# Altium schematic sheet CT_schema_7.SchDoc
size 299 x 271 mm
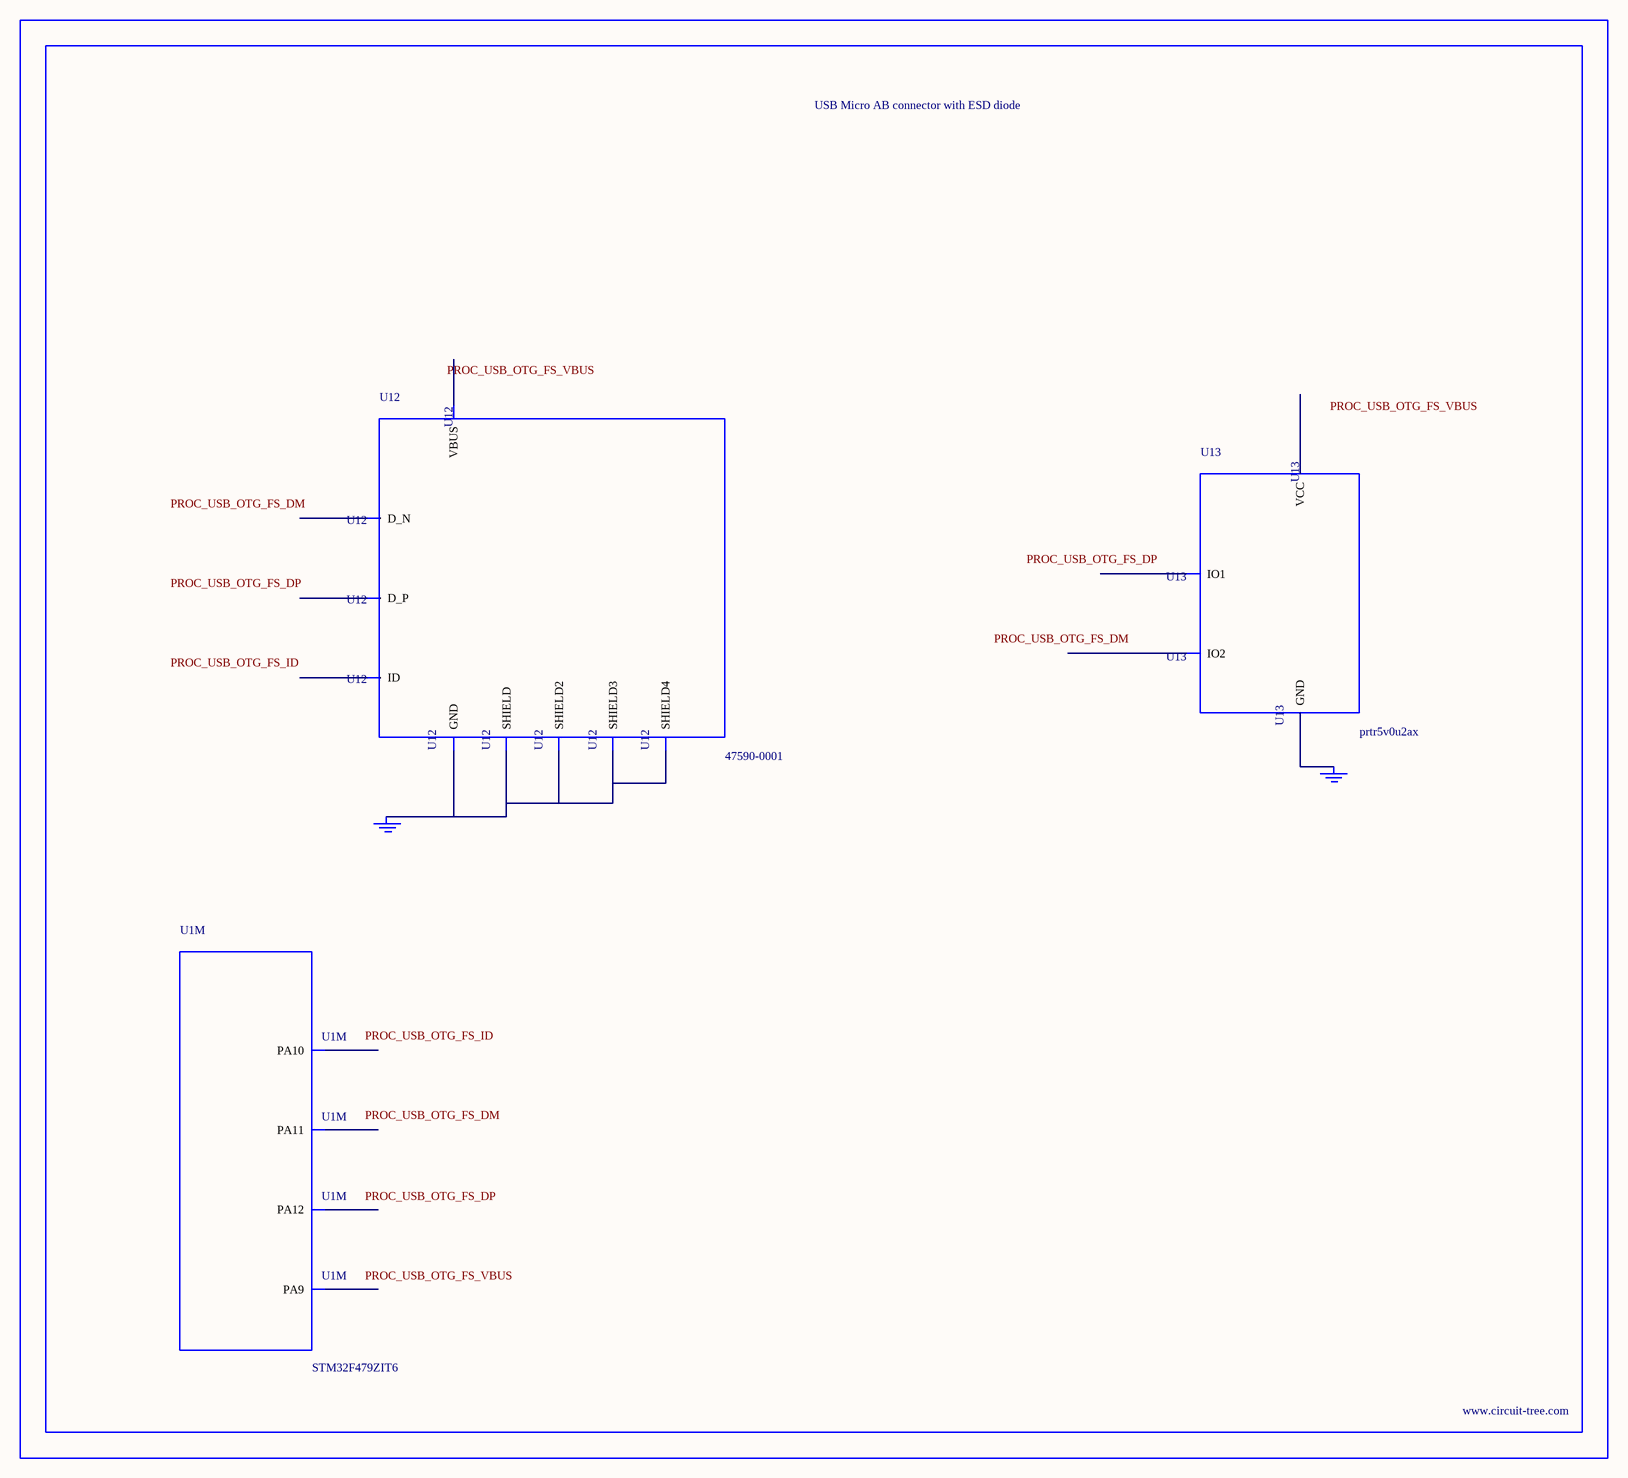
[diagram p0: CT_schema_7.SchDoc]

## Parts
BORDER6  (no value)
GND_INSTANCE_6_0  (no value)
GND_INSTANCE_6_1  (no value)
U1  STM32F479ZIT6  [LQFP144]  (part M of 13)
U12  47590-0001  [MICRO_USB_AB]
U13  prtr5v0u2ax  [SOT143B]

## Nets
NetGND_INSTANCE_6_0_0: GND_INSTANCE_6_0.0(GND) U12.5(GND) U12.6(SHIELD) U12.7(SHIELD2) U12.8(SHIELD3) U12.9(SHIELD4)
NetGND_INSTANCE_6_1_0: GND_INSTANCE_6_1.0(GND) U13.1(GND)

Not connected (* = marked no-connect by the designer): U1 103(PA9) 104(PA10) 105(PA11) 106(PA12); U12 1(VBUS) 2(D_N) 3(D_P) 4(ID); U13 2(IO1) 3(IO2) 4(VCC)

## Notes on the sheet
- Labels drawn without touching a wire or pin: PROC_USB_OTG_FS_DM, PROC_USB_OTG_FS_DP, PROC_USB_OTG_FS_ID, PROC_USB_OTG_FS_VBUS

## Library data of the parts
BORDER6 = BORDER_PAGE6
GND_INSTANCE_6_0 GND_INSTANCE_6_1 = GND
